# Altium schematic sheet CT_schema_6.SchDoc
size 305 x 256 mm
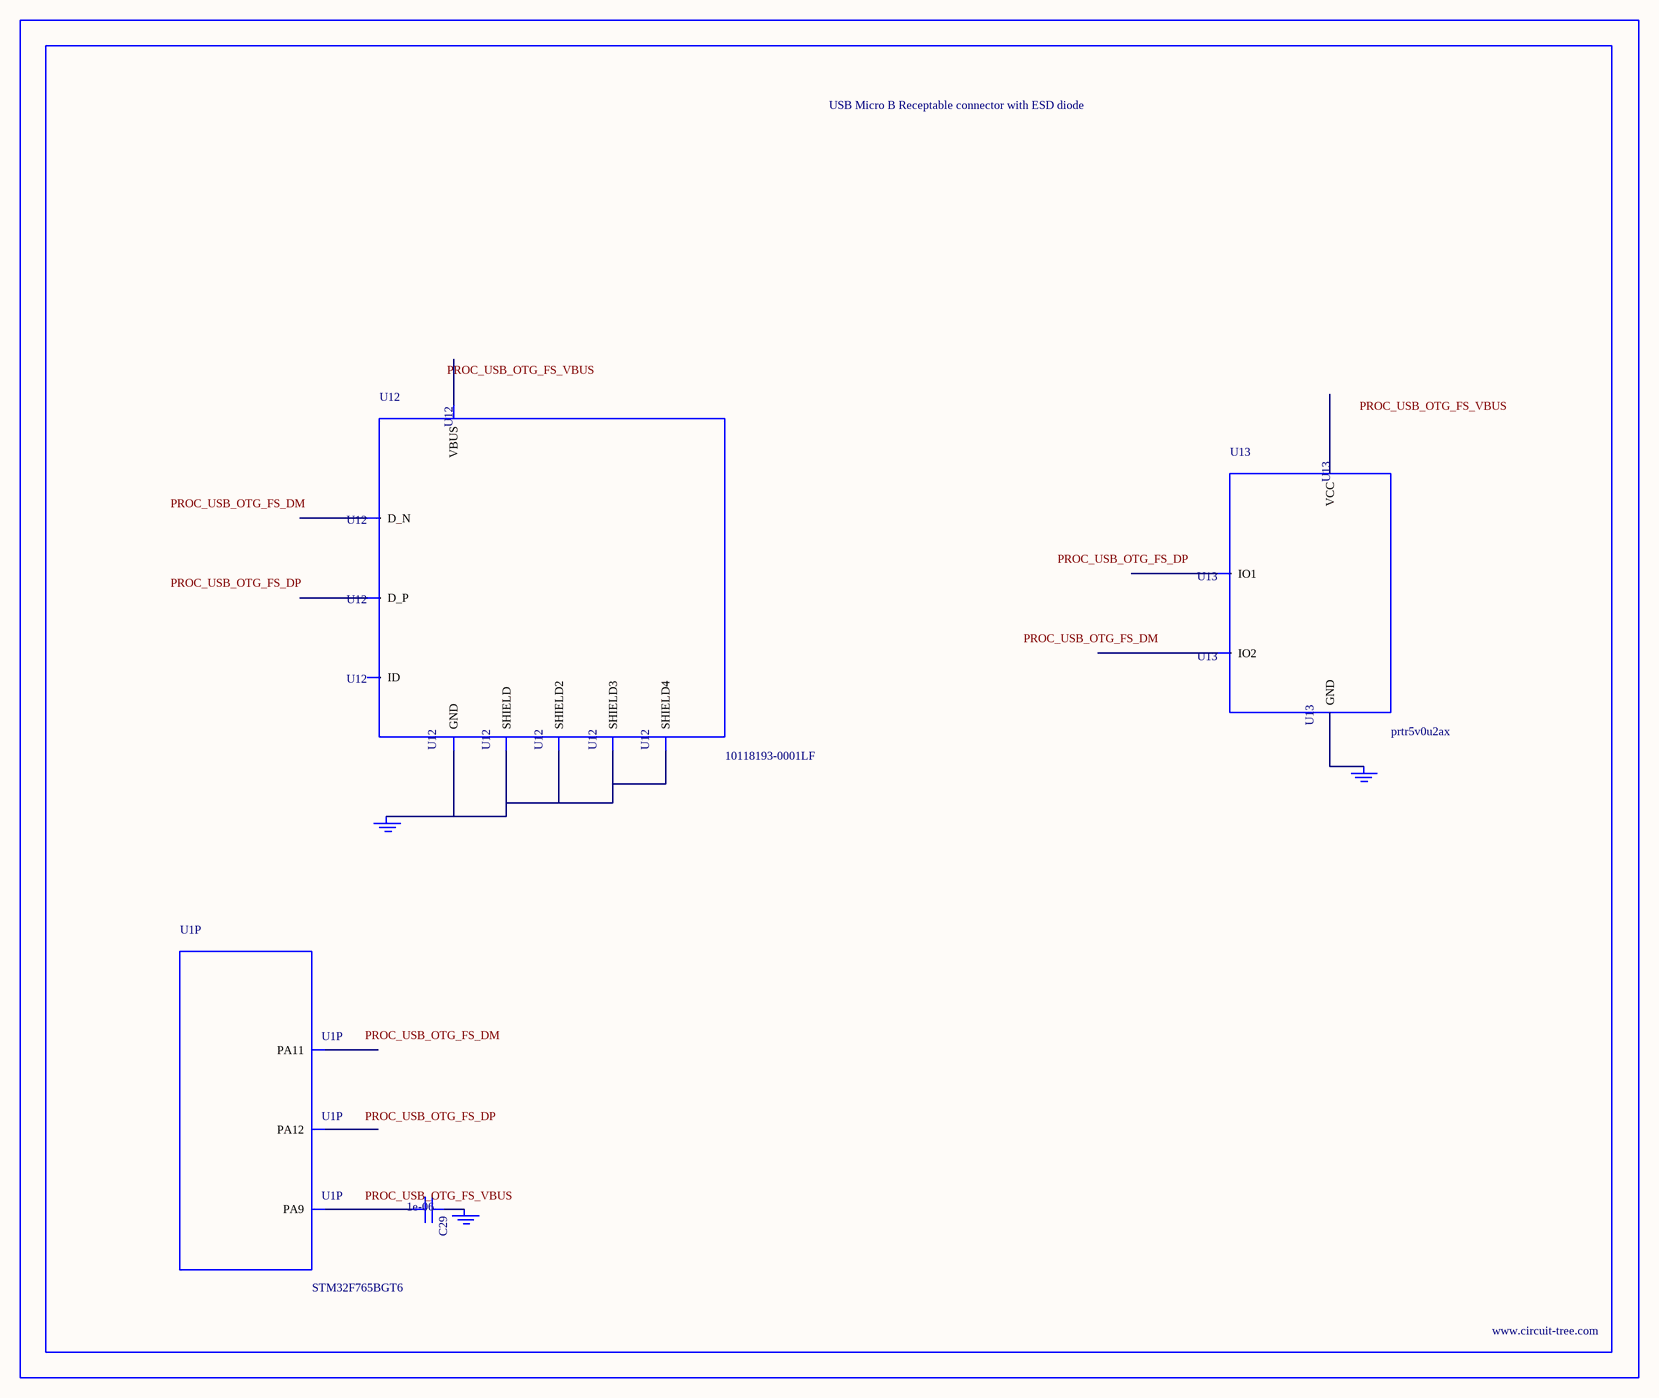
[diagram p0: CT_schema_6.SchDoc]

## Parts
BORDER5  (no value)
C29  1e-06  [C0603]
GND_INSTANCE_5_0  (no value)
GND_INSTANCE_5_1  (no value)
GND_INSTANCE_5_2  (no value)
U1  STM32F765BGT6  [LQFP208]  (part P of 16)
U12  10118193-0001LF  [FCI_10118193-0001LF]
U13  prtr5v0u2ax  [SOT143B]

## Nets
NetC29_1: C29.1 GND_INSTANCE_5_1.0(GND)
NetC29_2: C29.2 U1.143(PA9)
NetGND_INSTANCE_5_0_0: GND_INSTANCE_5_0.0(GND) U12.5(GND) U12.6(SHIELD) U12.7(SHIELD2) U12.8(SHIELD3) U12.9(SHIELD4)
NetGND_INSTANCE_5_2_0: GND_INSTANCE_5_2.0(GND) U13.1(GND)

Not connected (* = marked no-connect by the designer): U1 145(PA11) 146(PA12); U12 1(VBUS) 2(D_N) 3(D_P) 4(ID); U13 2(IO1) 3(IO2) 4(VCC)

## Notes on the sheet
- Labels drawn without touching a wire or pin: PROC_USB_OTG_FS_DM, PROC_USB_OTG_FS_DP, PROC_USB_OTG_FS_VBUS

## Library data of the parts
BORDER5 = BORDER_PAGE5
C29 = C0603C105K3RACTU
GND_INSTANCE_5_0-GND_INSTANCE_5_2 = GND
